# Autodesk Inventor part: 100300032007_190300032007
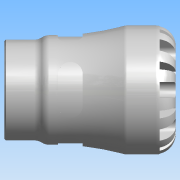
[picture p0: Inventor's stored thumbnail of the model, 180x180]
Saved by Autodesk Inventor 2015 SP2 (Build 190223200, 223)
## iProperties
Created: 2016-12
Part Number: 100300032007_190300032007
Material: PVC-Piping
Description: PLASSON FEMALE ADAPTOR 32X3/4" SERIES 1
Document SubType Name: Modeling
Designer: KIM
Mass: 664.223 g
Surface Area: 733.008 cm^2
Volume: 474.445 cm^3
Density: 1.4 g/cm^3
Appearance: Smooth - White
Author: KIM
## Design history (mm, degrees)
derived "1003.ipt"
feature "Solid1::1003.ipt"
tag "TaggingFeature1"
body "Solid1"
other parameters: "d0" = 77, "d1" = 22.68, "d2" = 32, "d4" = 58, "d6" = 54, "d8" = 49.3, "d13" = 7.2, "d14" = 7.2, "d15" = 0, "d17" = 360 deg, "d19" = 8 deg, "d20" = 0.64, "d21" = 0.64, "d22" = 8 deg, "d24" = 0, "d26" = 360 deg, "d32" = 5.8, "d33" = 5.8, "d39" = 0.72351, "d42" = 24.117, "d43" = 45.24, "d46" = 2.66667, "d47" = 18, "d48" = 22.91115, "d50" = 1.65, "d51" = 0.58, "d54" = 11.2, "d55" = 7.04, "d57" = 14.112, "d58" = 0, "d68" = 360 deg, "d72" = 0.64, "d74" = 0, "d76" = 9.52, "d_" = 32, "E_" = 58, "H_" = 77, "l_" = 54, "Rp" = 24.117, "l_2" = 18, "d9" = 9, "d11" = 58, "d49" = 5
